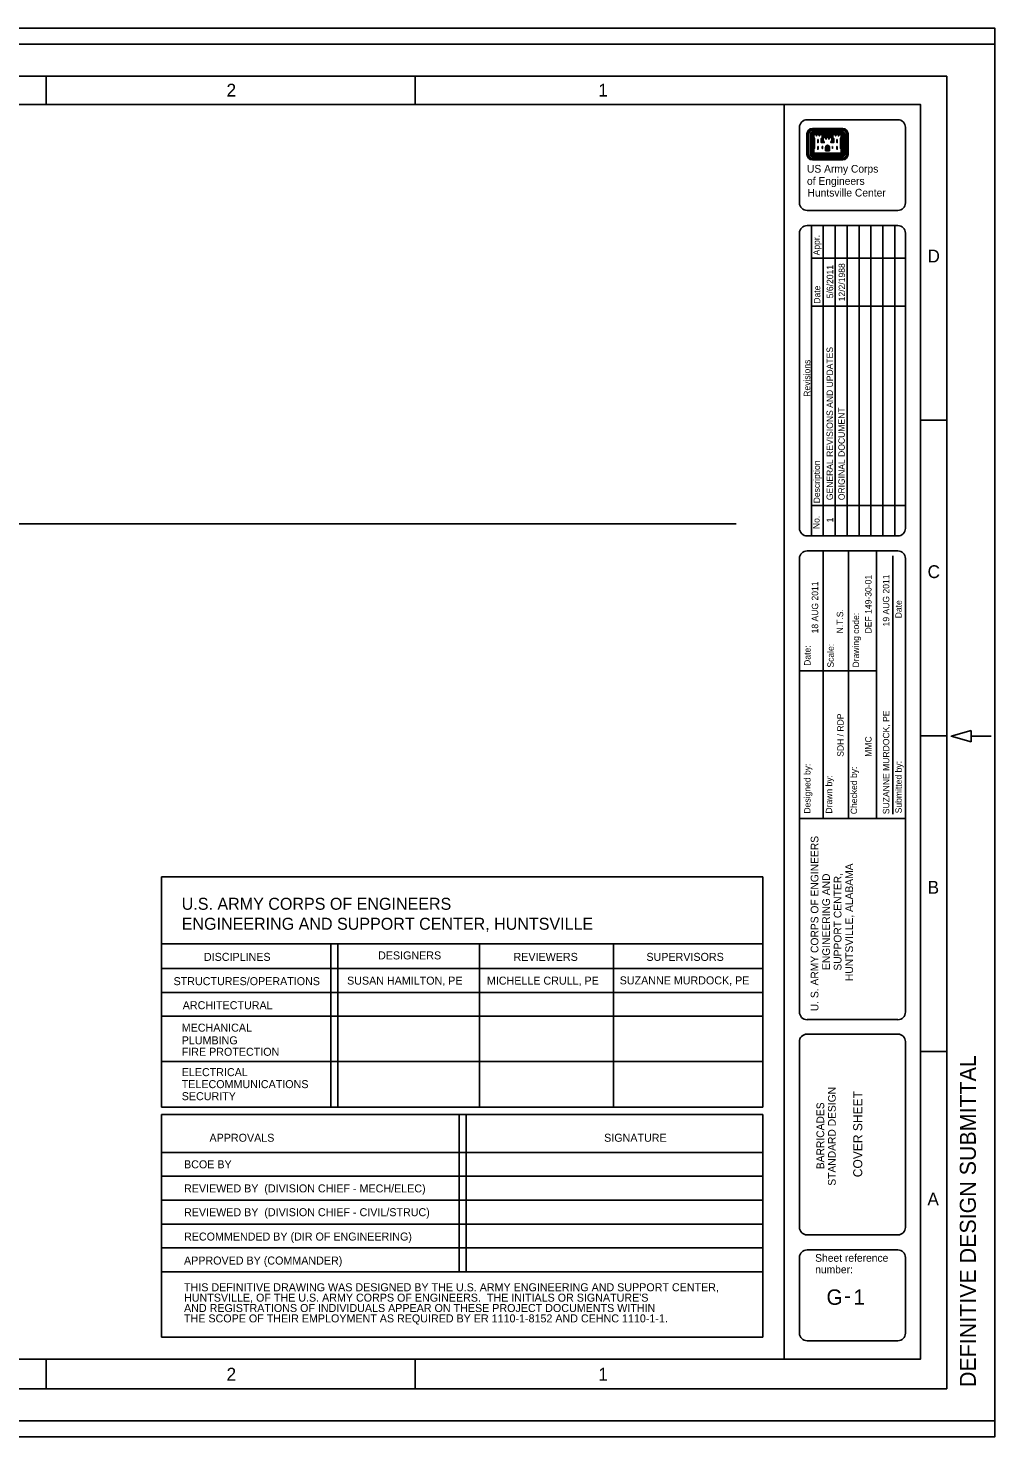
# Model space of a CAD drawing. Extents: x -0.04 to 2.79, y -0.02 to 1.81.
# Drawn here: x 1.534 to 2.792, y -0.021 to 1.813 of the extents above; entities that cross this region are included whole.
import ezdxf

# ---------------------------------------------------------------- set-up
doc = ezdxf.new("R2010")
doc.units = 0
for name, color, linetype in [('G-ANNO-INST', 7, 'Continuous'), ('G-ANNO-NPLT', 7, 'Continuous'), ('G-ANNO-PATT', 7, 'Continuous'), ('G-ANNO-PLOT', 7, 'Continuous'), ('G-ANNO-TEXT', 7, 'Continuous'), ('G-ANNO-TTLB', 7, 'Continuous'), ('Level 63', 7, 'Continuous')]:
    doc.layers.add(name, color=color, linetype=linetype)

msp = doc.modelspace()

# ---------------------------------------------------------------- linework, layer by layer
at = {"layer": 'G-ANNO-NPLT'}
msp.add_lwpolyline([(-0.0417, 1.8125), (2.7917, 1.8125), (2.7917, -0.0208), (-0.0417, -0.0208)], close=True, dxfattribs=at)
at = {"layer": 'G-ANNO-PATT'}
for p, q in [((1.7075, 0.7081), (2.4898, 0.7081)), ((1.7075, 0.408), (1.7075, 0.7081)), ((2.4898, 0.408), (2.4898, 0.7081)), ((1.7075, 0.6207), (2.4898, 0.6207)), ((1.928, 0.408), (1.928, 0.6207)), ((1.9371, 0.408), (1.9371, 0.6207)), ((2.1212, 0.408), (2.1212, 0.6207)), ((2.2957, 0.408), (2.2957, 0.6207)), ((1.7075, 0.5886), (2.4898, 0.5886)), ((1.7075, 0.5576), (2.4898, 0.5576)), ((1.7075, 0.5266), (2.4898, 0.5266)), ((1.7075, 0.4677), (2.4898, 0.4677)), ((1.7075, 0.408), (2.4898, 0.408)), ((1.7075, 0.1087), (1.7075, 0.3985)), ((1.7075, 0.3985), (2.4898, 0.3985)), ((2.0948, 0.1941), (2.0948, 0.3985)), ((2.104, 0.1941), (2.104, 0.3985)), ((2.4898, 0.1087), (2.4898, 0.3985)), ((1.7075, 0.3492), (2.4898, 0.3492)), ((1.7075, 0.3182), (2.4898, 0.3182)), ((1.7075, 0.2871), (2.4898, 0.2871)), ((1.7075, 0.2561), (2.4898, 0.2561)), ((1.7075, 0.2251), (2.4898, 0.2251)), ((1.7075, 0.1941), (2.4898, 0.1941)), ((1.7075, 0.1087), (2.4898, 0.1087))]:
    msp.add_line(p, q, dxfattribs=at)
at = {"layer": 'G-ANNO-PLOT'}
for p, q in [((2.7917, 1.8125), (-0.0417, 1.8125)), ((2.7917, 1.8125), (2.7917, -0.0208)), ((2.7917, -0.0208), (-0.0417, -0.0208))]:
    msp.add_line(p, q, dxfattribs=at)
msp.add_lwpolyline([(0, 0), (2.7917, 0), (2.7917, 1.7917), (0, 1.7917)], close=True, dxfattribs=at)
at = {"layer": 'G-ANNO-TTLB'}
for p, q in [((1.5578, 1.7131), (1.5578, 1.75)), ((2.0378, 1.7131), (2.0378, 1.75)), ((2.5178, 0.0803), (2.5178, 1.7131)), ((2.5473, 1.6749), (2.5473, 1.6483)), ((2.5477, 1.6749), (2.5477, 1.6483)), ((2.5484, 1.6749), (2.5484, 1.6483)), ((2.5489, 1.6749), (2.5489, 1.6483)), ((2.5494, 1.6749), (2.5494, 1.6483)), ((2.5517, 1.6749), (2.5517, 1.6483)), ((2.5523, 1.6749), (2.5523, 1.6483)), ((2.5528, 1.6749), (2.5528, 1.6483)), ((2.5534, 1.6749), (2.5534, 1.6483)), ((2.554, 1.6749), (2.554, 1.6483)), ((2.5938, 1.6819), (2.5543, 1.6819)), ((2.5938, 1.6815), (2.5543, 1.6815)), ((2.5938, 1.6809), (2.5543, 1.6809)), ((2.5938, 1.6804), (2.5543, 1.6804)), ((2.5938, 1.6798), (2.5543, 1.6798)), ((2.5938, 1.6776), (2.5543, 1.6776)), ((2.5938, 1.677), (2.5543, 1.677)), ((2.5938, 1.6764), (2.5543, 1.6764)), ((2.5938, 1.6758), (2.5543, 1.6758)), ((2.5938, 1.6753), (2.5543, 1.6753)), ((2.5545, 1.6749), (2.5545, 1.6484)), ((2.5551, 1.6749), (2.5551, 1.649)), ((2.5555, 1.6692), (2.5555, 1.6556)), ((2.5561, 1.6686), (2.5561, 1.6563)), ((2.5679, 1.6747), (2.5801, 1.6747)), ((2.5679, 1.6742), (2.5801, 1.6742)), ((2.5679, 1.6737), (2.5801, 1.6737)), ((2.5679, 1.6731), (2.5801, 1.6731)), ((2.5679, 1.6725), (2.5801, 1.6725)), ((2.5679, 1.672), (2.5801, 1.672)), ((2.5679, 1.6714), (2.5801, 1.6714)), ((2.592, 1.6686), (2.592, 1.6563)), ((2.5925, 1.6692), (2.5925, 1.6557)), ((2.593, 1.6749), (2.593, 1.649)), ((2.5935, 1.6749), (2.5935, 1.6484)), ((2.5941, 1.6749), (2.5941, 1.6483)), ((2.5947, 1.6749), (2.5947, 1.6483)), ((2.5953, 1.6749), (2.5953, 1.6483)), ((2.5958, 1.6749), (2.5958, 1.6483)), ((2.5964, 1.6749), (2.5964, 1.6483)), ((2.5986, 1.6749), (2.5986, 1.6483)), ((2.5992, 1.6749), (2.5992, 1.6483)), ((2.5997, 1.6749), (2.5997, 1.6483)), ((2.6003, 1.6749), (2.6003, 1.6483)), ((2.6007, 1.6749), (2.6007, 1.6483)), ((2.5714, 1.6528), (2.5714, 1.6572)), ((2.5714, 1.6528), (2.5767, 1.6528)), ((2.5719, 1.6528), (2.5719, 1.6572)), ((2.5725, 1.6528), (2.5725, 1.6572)), ((2.5731, 1.6528), (2.5731, 1.6572)), ((2.5737, 1.6528), (2.5737, 1.6572)), ((2.5744, 1.6528), (2.5744, 1.6572)), ((2.575, 1.6528), (2.575, 1.6572)), ((2.5755, 1.6528), (2.5755, 1.6572)), ((2.5761, 1.6528), (2.5761, 1.6572)), ((2.5767, 1.6528), (2.5767, 1.6572)), ((2.5938, 1.6478), (2.5543, 1.6478)), ((2.5938, 1.6473), (2.5543, 1.6473)), ((2.5938, 1.6467), (2.5543, 1.6467)), ((2.5938, 1.6462), (2.5543, 1.6462)), ((2.5938, 1.6456), (2.5543, 1.6456)), ((2.5938, 1.6433), (2.5543, 1.6433)), ((2.5938, 1.6428), (2.5543, 1.6428)), ((2.5938, 1.6423), (2.5543, 1.6423)), ((2.5938, 1.6417), (2.5543, 1.6417)), ((2.5938, 1.6412), (2.5543, 1.6412)), ((2.5935, 1.6484), (2.5545, 1.6484)), ((2.593, 1.649), (2.5551, 1.649)), ((2.5532, 1.5557), (2.5532, 1.1517)), ((2.5686, 1.5557), (2.5686, 1.1517)), ((2.5842, 1.5557), (2.5842, 1.1517)), ((2.5996, 1.5557), (2.5996, 1.1517)), ((2.6151, 1.5557), (2.6151, 1.1517)), ((2.6306, 1.5557), (2.6306, 1.1517)), ((2.646, 1.5557), (2.646, 1.1517)), ((2.6615, 1.5557), (2.6615, 1.1517)), ((2.5532, 1.513), (2.6754, 1.513)), ((2.5532, 1.4507), (2.6754, 1.4507)), ((2.695, 1.3022), (2.7292, 1.3022)), ((2.5532, 1.1911), (2.6754, 1.1911)), ((2.5685, 1.1321), (2.5685, 0.976)), ((2.6014, 1.1321), (2.6014, 0.976)), ((2.6377, 1.1321), (2.6377, 0.7837)), ((2.659, 0.7895), (2.659, 1.1258)), ((2.6377, 0.976), (2.5376, 0.976)), ((2.5685, 0.976), (2.5685, 0.7837)), ((2.6014, 0.976), (2.6014, 0.7837)), ((2.695, 0.8914), (2.7292, 0.8914)), ((2.7609, 0.891), (2.787, 0.891)), ((2.6754, 0.7837), (2.5376, 0.7837)), ((2.5474, 0.5221), (2.6655, 0.5221)), ((2.695, 0.4806), (2.7292, 0.4806)), ((1.5578, 0.0418), (1.5578, 0.0803)), ((2.0378, 0.0418), (2.0378, 0.0803))]:
    msp.add_line(p, q, dxfattribs=at)
for points in [[(0.0833, 0.0417), (2.7292, 0.0417), (2.7292, 1.75), (0.2515, 1.75)], [(0.1166, 0.0803), (2.695, 0.0803), (2.695, 1.7131), (0.1166, 1.7131)], [(2.5474, 1.6934), (2.6655, 1.6934)], [(2.5376, 1.5851), (2.5376, 1.6835)], [(2.5555, 1.6749), (2.5555, 1.6698), (2.5567, 1.6686), (2.5567, 1.6563), (2.5555, 1.6551), (2.5555, 1.6494), (2.5926, 1.6494), (2.5926, 1.6551), (2.5914, 1.6563), (2.5914, 1.6686), (2.5926, 1.6698), (2.5926, 1.6749), (2.5877, 1.6749), (2.5839, 1.6749), (2.5804, 1.6749), (2.5804, 1.6698), (2.5817, 1.6686), (2.5817, 1.6642), (2.5789, 1.6642), (2.5789, 1.6646), (2.5801, 1.6657), (2.5801, 1.6708), (2.5752, 1.6708), (2.5714, 1.6708), (2.5679, 1.6708), (2.5679, 1.6657), (2.5691, 1.6646), (2.5691, 1.6642), (2.5664, 1.6642), (2.5664, 1.6686), (2.5676, 1.6698), (2.5676, 1.6749), (2.5626, 1.6749), (2.5589, 1.6749), (2.5555, 1.6749)], [(2.5561, 1.6743), (2.5561, 1.67), (2.5573, 1.6688), (2.5573, 1.656), (2.5561, 1.6549), (2.5561, 1.65), (2.592, 1.65), (2.592, 1.6549), (2.5909, 1.656), (2.5909, 1.6688), (2.592, 1.67), (2.592, 1.6743), (2.5886, 1.6743), (2.5886, 1.6723), (2.5883, 1.6723), (2.5883, 1.6743), (2.5848, 1.6743), (2.5848, 1.6723), (2.5845, 1.6723), (2.5845, 1.6743), (2.581, 1.6743), (2.581, 1.67), (2.5822, 1.6688), (2.5822, 1.6636), (2.5784, 1.6636), (2.5784, 1.6648), (2.5796, 1.6659), (2.5796, 1.6703), (2.5761, 1.6703), (2.5761, 1.6682), (2.5757, 1.6682), (2.5757, 1.6703), (2.5723, 1.6703), (2.5723, 1.6682), (2.5719, 1.6682), (2.5719, 1.6703), (2.5685, 1.6703), (2.5685, 1.6659), (2.5697, 1.6648), (2.5697, 1.6636), (2.5658, 1.6636), (2.5658, 1.6688), (2.5671, 1.67), (2.5671, 1.6743), (2.5636, 1.6743), (2.5636, 1.6723), (2.5633, 1.6723), (2.5633, 1.6743), (2.5598, 1.6743), (2.5598, 1.6723), (2.5595, 1.6723), (2.5595, 1.6743), (2.5561, 1.6743)], [(2.5673, 1.6687), (2.567, 1.6684), (2.567, 1.6647), (2.5682, 1.6647), (2.5674, 1.6655), (2.5674, 1.6688)], [(2.5807, 1.6687), (2.581, 1.6684), (2.581, 1.6647), (2.5799, 1.6647), (2.5807, 1.6655), (2.5807, 1.6688)], [(2.6754, 1.6835), (2.6754, 1.5851)], [(2.5614, 1.6674), (2.5614, 1.6636), (2.5617, 1.6636), (2.5617, 1.6674), (2.5614, 1.6674)], [(2.5614, 1.6587), (2.5614, 1.6549), (2.5617, 1.6549), (2.5617, 1.6587), (2.5614, 1.6587)], [(2.5673, 1.6587), (2.5673, 1.6561), (2.5677, 1.6561), (2.5677, 1.6587), (2.5673, 1.6587)], [(2.5807, 1.6587), (2.5807, 1.6561), (2.5804, 1.6561), (2.5804, 1.6587), (2.5807, 1.6587)], [(2.5867, 1.6674), (2.5867, 1.6636), (2.5863, 1.6636), (2.5863, 1.6674), (2.5867, 1.6674)], [(2.5867, 1.6587), (2.5867, 1.6549), (2.5863, 1.6549), (2.5863, 1.6587), (2.5867, 1.6587)], [(2.6655, 1.5753), (2.5474, 1.5753)], [(2.5376, 1.5458), (2.5376, 1.1615)], [(2.6655, 1.5557), (2.5474, 1.5557)], [(2.6754, 1.1615), (2.6754, 1.5458)], [(2.5474, 1.1517), (2.6655, 1.1517)], [(2.5376, 1.1223), (2.5376, 0.5321)], [(2.6655, 1.1321), (2.5474, 1.1321)], [(2.6754, 0.5319), (2.6754, 1.1223)], [(2.6655, 0.5033), (2.5474, 0.5033)], [(2.5376, 0.493), (2.5376, 0.2518)], [(2.6754, 0.2518), (2.6754, 0.4935)], [(2.5474, 0.242), (2.6655, 0.242)], [(2.5474, 0.2224), (2.6655, 0.2224)], [(2.5376, 0.1141), (2.5376, 0.2126)], [(2.6754, 0.2126), (2.6754, 0.1141)], [(2.6655, 0.1043), (2.5474, 0.1043)]]:
    msp.add_lwpolyline(points, dxfattribs=at)
msp.add_lwpolyline([(2.7609, 0.8983), (2.735, 0.891), (2.7609, 0.8837)], close=True, dxfattribs=at)
for centre, major_axis, start_param, end_param in [((2.5474, 1.6835), (-0.00984, 0), 4.712389, 6.283185), ((2.6655, 1.6835), (-0.00984, 0), 3.141593, 4.712389), ((2.5543, 1.6749), (-0.00696, 0), 4.712389, 6.283185), ((2.5543, 1.6749), (-0.00656, 0), 4.712389, 6.283185), ((2.5543, 1.6749), (-0.006, 0), 4.712389, 6.283185), ((2.5543, 1.6749), (-0.00543, 0), 4.712389, 6.283185), ((2.5543, 1.6749), (-0.00487, 0), 4.712389, 6.283185), ((2.5543, 1.6749), (-0.00261, 0), 4.712389, 6.283185), ((2.5543, 1.6749), (-0.00205, 0), 4.712389, 6.283185), ((2.5543, 1.6749), (-0.00148, 0), 4.712389, 6.283185), ((2.5543, 1.6749), (0.000919, 0), 1.570796, 3.141593), ((2.5543, 1.6749), (-0.000355, 0), 4.712389, 6.283185), ((2.5938, 1.6749), (-0.00696, 0), 3.141593, 4.712389), ((2.5938, 1.6749), (0.00656, 0), 0, 1.570796), ((2.5938, 1.6749), (0.006, 0), 0, 1.570796), ((2.5938, 1.6749), (0.00543, 0), 0, 1.570796), ((2.5938, 1.6749), (0.00487, 0), 0, 1.570796), ((2.5938, 1.6749), (-0.00261, 0), 3.141593, 4.712389), ((2.5938, 1.6749), (-0.00205, 0), 3.141593, 4.712389), ((2.5938, 1.6749), (-0.00148, 0), 3.141593, 4.712389), ((2.5938, 1.6749), (-0.000919, 0), 3.141593, 4.712389), ((2.5938, 1.6749), (-0.000355, 0), 3.141593, 4.712389), ((2.575, 1.6569), (0.00361, 0), 1.844255, 3.072783), ((2.575, 1.6569), (-0.00304, 0), 4.947481, 6.214375), ((2.575, 1.6569), (-0.00248, 0), 4.947481, 6.214375), ((2.575, 1.6569), (-0.00192, 0), 4.947481, 6.214375), ((2.5731, 1.6569), (0.00135, 0), 0.06881, 1.335704), ((2.5731, 1.6569), (0.00192, 0), 0.06881, 1.335704), ((2.5731, 1.6569), (-0.00248, 0), 3.210403, 4.477297), ((2.575, 1.6569), (-0.00135, 0), 4.947481, 6.214375), ((2.5731, 1.6569), (0.00304, 0), 0.06881, 1.335704), ((2.5731, 1.6569), (0.00361, 0), 0.06881, 1.298435), ((2.5543, 1.6482), (0.00696, 0), 3.141593, 4.712389), ((2.5543, 1.6482), (0.00656, 0), 3.141593, 4.712389), ((2.5543, 1.6482), (-0.006, 0), 0, 1.570796), ((2.5543, 1.6482), (0.00543, 0), 3.141593, 4.712389), ((2.5543, 1.6482), (0.00487, 0), 3.141593, 4.712389), ((2.5543, 1.6482), (0.00261, 0), 3.141593, 4.712389), ((2.5543, 1.6482), (0.00205, 0), 3.141593, 4.712389), ((2.5543, 1.6482), (0.00148, 0), 3.141593, 4.712389), ((2.5543, 1.6482), (0.000919, 0), 3.141593, 4.712389), ((2.5543, 1.6482), (0.000355, 0), 3.141593, 4.712389), ((2.5938, 1.6482), (0.00696, 0), 4.712389, 6.283185), ((2.5938, 1.6482), (0.00261, 0), 4.712389, 6.283185), ((2.5938, 1.6482), (0.00205, 0), 4.712389, 6.283185), ((2.5938, 1.6482), (0.00148, 0), 4.712389, 6.283185), ((2.5938, 1.6482), (0.000919, 0), 4.712389, 6.283185), ((2.5938, 1.6482), (0.000355, 0), 4.712389, 6.283185), ((2.5938, 1.6482), (0.00487, 0), 4.712389, 6.283185), ((2.5938, 1.6482), (0.00543, 0), 4.712389, 6.283185), ((2.5938, 1.6482), (0.006, 0), 4.712389, 6.283185), ((2.5938, 1.6482), (0.00656, 0), 4.712389, 6.283185), ((2.5474, 1.5851), (-0.00984, 0), 0, 1.570796), ((2.6655, 1.5851), (0.00984, 0), 4.712389, 6.283185), ((2.5474, 1.5458), (-0.00984, 0), 4.712389, 6.281588), ((2.6655, 1.5458), (-0.00984, 0), 3.141593, 4.712389), ((2.5474, 1.1615), (-0.00984, 0), 0, 1.570796), ((2.6655, 1.1615), (0.00984, 0), 4.712389, 6.283185), ((2.5474, 1.1223), (-0.00984, 0), 4.712389, 6.283185), ((2.6655, 1.1223), (-0.00984, 0), 3.141593, 4.712389), ((2.5474, 0.5319), (-0.00984, 0), 6.267222, 7.853982), ((2.6655, 0.5319), (0.00984, 0), 4.712389, 6.283185), ((2.5474, 0.4935), (-0.00984, 0), 4.712389, 6.327939), ((2.6655, 0.4935), (0.00984, 0), 0, 1.570796), ((2.5474, 0.2518), (-0.00984, 0), 0, 1.570796), ((2.6655, 0.2518), (0.00984, 0), 4.712389, 6.283185), ((2.5474, 0.2126), (-0.00984, 0), 4.712389, 6.283185), ((2.6655, 0.2126), (0.00984, 0), 0, 1.570796), ((2.5474, 0.1141), (-0.00984, 0), 0, 1.570796), ((2.6655, 0.1141), (0.00984, 0), 4.712389, 6.283185)]:
    msp.add_ellipse(centre, major_axis=major_axis, ratio=0.999936, start_param=start_param, end_param=end_param, dxfattribs=at)
at = {"layer": 'Level 63'}
msp.add_line((0.1695, 1.1676), (2.4553, 1.1676), dxfattribs=at)

# ---------------------------------------------------------------- texts
at = {"layer": 'G-ANNO-INST'}
for s, p in [('G', (2.5727, 0.151)), ('1', (2.6078, 0.151)), ('-', (2.5954, 0.1531))]:
    msp.add_text(s, height=0.02, dxfattribs=at).set_placement(p)
at = {"layer": 'G-ANNO-TEXT'}
for s, height, p in [('U.S. ARMY CORPS OF ENGINEERS', 0.015625, (1.734, 0.6651)), ('ENGINEERING AND SUPPORT CENTER, HUNTSVILLE', 0.015625, (1.734, 0.6391)), ('DISCIPLINES', 0.010417, (1.7629, 0.5986)), ('DESIGNERS', 0.01042, (1.9894, 0.6005)), ('REVIEWERS', 0.01042, (2.1656, 0.5986)), ('SUPERVISORS', 0.010417, (2.3385, 0.5986)), ('STRUCTURES/OPERATIONS', 0.010417, (1.7234, 0.567)), ('SUSAN HAMILTON, PE', 0.010417, (1.9491, 0.5677)), ('MICHELLE CRULL, PE', 0.010417, (2.131, 0.5677)), ('SUZANNE MURDOCK, PE', 0.010417, (2.3037, 0.568)), ('ARCHITECTURAL', 0.010417, (1.7353, 0.5357)), ('MECHANICAL', 0.01042, (1.734, 0.5065)), ('PLUMBING', 0.01042, (1.734, 0.49)), ('FIRE PROTECTION', 0.010417, (1.734, 0.4751)), ('ELECTRICAL', 0.01042, (1.734, 0.4486)), ('TELECOMMUNICATIONS', 0.010417, (1.734, 0.433)), ('SECURITY', 0.01042, (1.734, 0.4173)), ('APPROVALS', 0.01042, (1.7701, 0.3632)), ('SIGNATURE', 0.01042, (2.2835, 0.3632)), ('BCOE BY', 0.01042, (1.737, 0.3286)), ('REVIEWED BY  (DIVISION CHIEF - MECH/ELEC)', 0.010417, (1.737, 0.2973)), ('REVIEWED BY  (DIVISION CHIEF - CIVIL/STRUC)', 0.010417, (1.737, 0.2663)), ('RECOMMENDED BY (DIR OF ENGINEERING)', 0.010417, (1.737, 0.2346)), ('APPROVED BY (COMMANDER)', 0.010417, (1.737, 0.2034)), ('THIS DEFINITIVE DRAWING WAS DESIGNED BY THE U.S. ARMY ENGINEERING AND SUPPORT CENTER,', 0.010417, (1.737, 0.1686)), ("HUNTSVILLE, OF THE U.S. ARMY CORPS OF ENGINEERS.  THE INITIALS OR SIGNATURE'S", 0.010417, (1.737, 0.1551)), ('AND REGISTRATIONS OF INDIVIDUALS APPEAR ON THESE PROJECT DOCUMENTS WITHIN', 0.010417, (1.737, 0.1416)), ('THE SCOPE OF THEIR EMPLOYMENT AS REQUIRED BY ER 1110-1-8152 AND CEHNC 1110-1-1.', 0.010417, (1.737, 0.1281))]:
    msp.add_text(s, height=height, dxfattribs=at).set_placement(p)
at = {"layer": 'G-ANNO-TTLB'}
for s, height, p in [('2', 0.0167, (1.7923, 1.7235)), ('1', 0.0167, (2.2759, 1.7235)), ('US Army Corps', 0.01, (2.5473, 1.6245)), ('of Engineers', 0.01, (2.5473, 1.6086)), ('Huntsville Center', 0.01, (2.548, 1.5934)), ('D', 0.0167, (2.7041, 1.5076)), ('D', 0.0167, (2.7041, 1.5076)), ('C', 0.0167, (2.7042, 1.0968)), ('B', 0.0167, (2.7043, 0.686)), ('A', 0.0167, (2.704, 0.2804)), ('Sheet reference', 0.01, (2.558, 0.207)), ('number:', 0.01, (2.558, 0.192)), ('2', 0.0167, (1.7923, 0.0523)), ('1', 0.0167, (2.2759, 0.0523))]:
    msp.add_text(s, height=height, dxfattribs=at).set_placement(p)
for s, height, p in [('Appr.', 0.00833, (2.5639, 1.5168)), ('5/6/2011', 0.00833, (2.5814, 1.461)), ('12/2/1988', 0.00833, (2.5968, 1.457)), ('Date', 0.00833, (2.5646, 1.4539)), ('GENERAL REVISIONS AND UPDATES', 0.008333, (2.5811, 1.1982)), ('Revisions', 0.00833, (2.5515, 1.3328)), ('ORIGINAL DOCUMENT', 0.008333, (2.5965, 1.1982)), ('Description', 0.008333, (2.5642, 1.1941)), ('No.', 0.00833, (2.5637, 1.1606)), ('1', 0.00833, (2.5814, 1.1693)), ('DEF 149-30-01', 0.008333, (2.6313, 1.0248)), ('19 AUG 2011', 0.008333, (2.6544, 1.0339)), ('18 AUG 2011', 0.008333, (2.5619, 1.0248)), ('Submitted by:                                                            Date', 0.008333, (2.6706, 0.7906)), ('N.T.S.', 0.00833, (2.5944, 1.0248)), ('Drawing code:', 0.008333, (2.6151, 0.9804)), ('Scale:', 0.00833, (2.5822, 0.9803)), ('Date:', 0.00833, (2.552, 0.9826)), ('SDH / RDP', 0.00833, (2.595, 0.8642)), ('SUZANNE MURDOCK, PE', 0.008333, (2.6544, 0.7895)), ('MMC', 0.00833, (2.6313, 0.8642)), ('Designed by:', 0.008333, (2.5519, 0.7903)), ('Checked by:', 0.008333, (2.6125, 0.7895)), ('Drawn by:', 0.00833, (2.5801, 0.7903)), ('U. S. ARMY CORPS OF ENGINEERS', 0.01, (2.5622, 0.5331)), ('HUNTSVILLE, ALABAMA', 0.01, (2.6072, 0.5723)), ('ENGINEERING AND', 0.01, (2.5772, 0.5867)), ('SUPPORT CENTER,', 0.01, (2.5922, 0.5859)), ('DEFINITIVE DESIGN SUBMITTAL', 0.020833, (2.767, 0.044)), ('STANDARD DESIGN', 0.01, (2.5847, 0.306)), ('COVER SHEET', 0.0117, (2.6192, 0.317)), ('BARRICADES', 0.01, (2.5697, 0.3275))]:
    msp.add_text(s, height=height, rotation=90, dxfattribs=at).set_placement(p)

doc.saveas('drawing.dxf')
